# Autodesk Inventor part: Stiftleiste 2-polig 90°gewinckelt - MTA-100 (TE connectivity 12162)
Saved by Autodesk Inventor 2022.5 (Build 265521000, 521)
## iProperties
Created: 2024-12
Part Number: Stiftleiste 2-polig 90°gewinckelt - MTA-100 (TE connectivity 12162)
Material: Generic
Document SubType Name: Modeling
Designer: AdminForWorker
Density: 1 g/cm^3
Appearance: Default
Title: Stiftleiste 2-polig 90°gewinckelt - MTA-100 (TE connectivity 12162)
Author: AdminForWorker
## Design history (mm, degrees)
feature "Body1"
body "Solid1"
